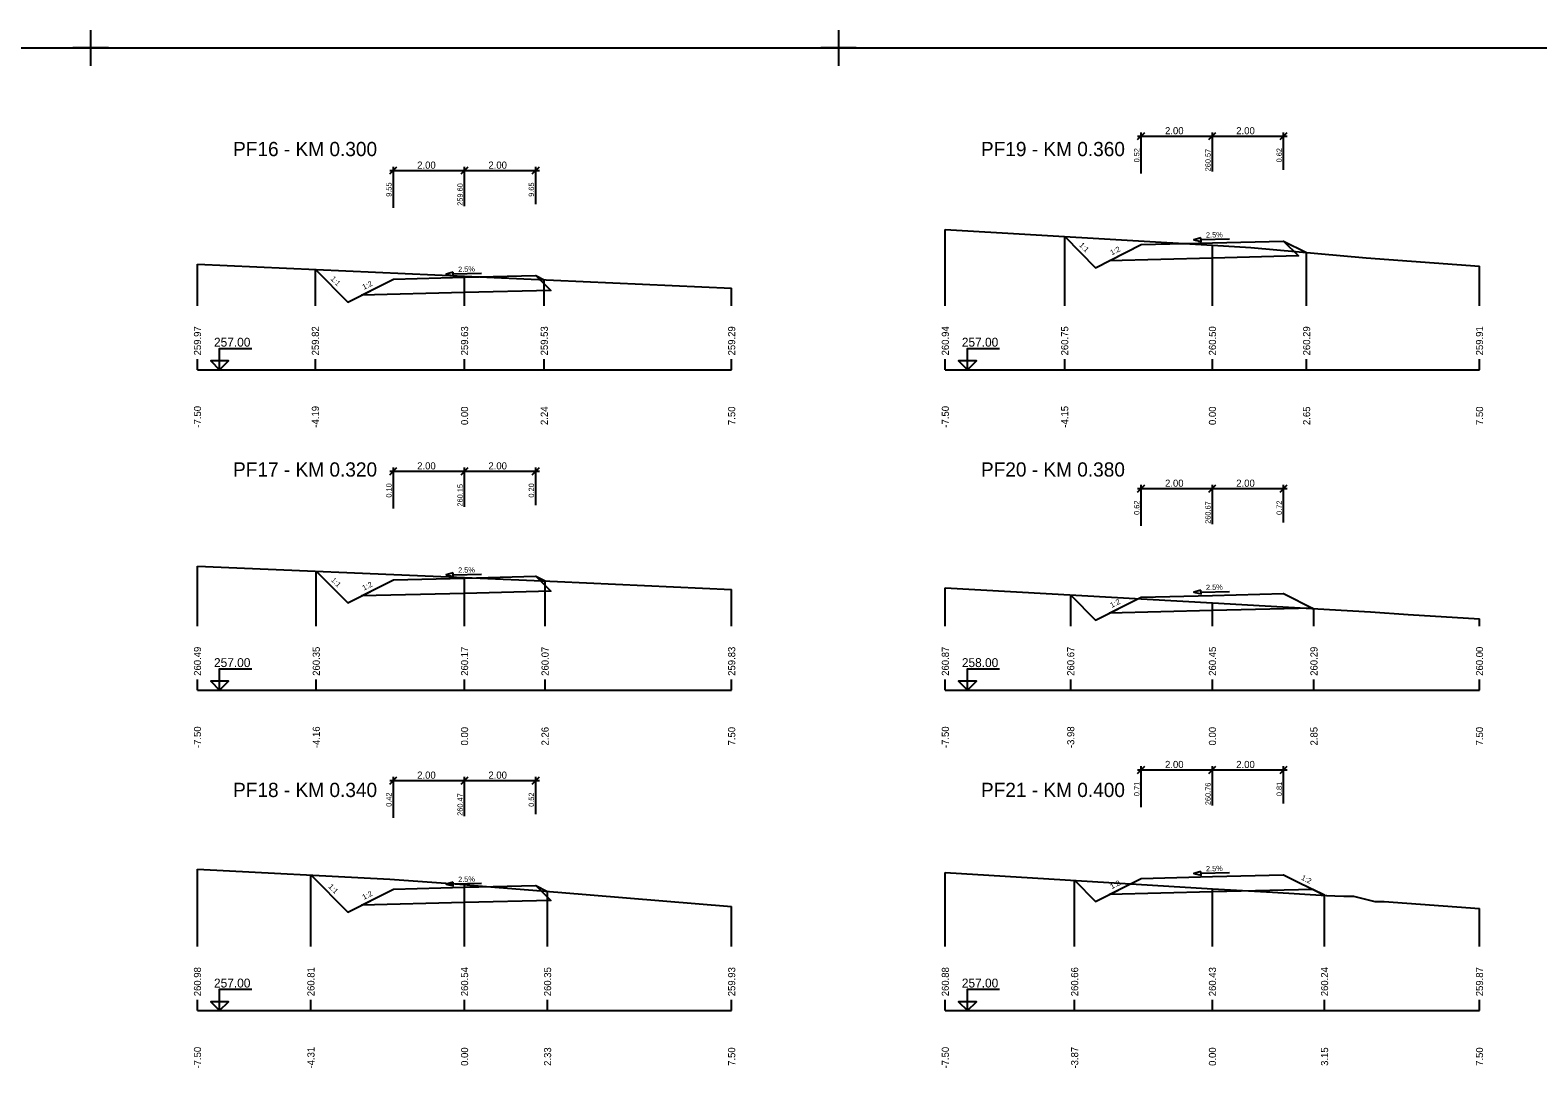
# Model space of a CAD drawing. Extents: x -5 to 1895, y -2 to 602.
# Drawn here: x 1033 to 1456.4, y 308.1 to 602.4 of the extents above; entities that cross this region are included whole.
import ezdxf

# ---------------------------------------------------------------- set-up
doc = ezdxf.new("R2010")
doc.units = 0
for name, color, linetype in [('KOTA', 7, 'Continuous'), ('KOTA_DELKY', 7, 'Continuous'), ('KOTA_DELKY_CONT', 7, 'Continuous'), ('NS_TELESO_VOZOVKY', 7, 'Continuous'), ('NS_V_PF', 7, 'Continuous'), ('REZY_PF_PUVODNI', 7, 'Continuous'), ('SESTAVY_REZU_PF', 7, 'Continuous'), ('SKLON', 7, 'Continuous'), ('SVK', 7, 'Continuous')]:
    doc.layers.add(name, color=color, linetype=linetype)

msp = doc.modelspace()

# ---------------------------------------------------------------- linework, layer by layer
for p, q in [((1050, 602.39), (1050, 592.39)), ((1050, 602.39), (1050, 592.39)), ((1050, 602.39), (1050, 592.39)), ((1050, 602.39), (1050, 592.39)), ((1050, 602.39), (1050, 592.39)), ((1050, 602.39), (1050, 592.39)), ((1050, 602.39), (1050, 592.39)), ((1050, 602.39), (1050, 592.39)), ((1050, 602.39), (1050, 592.39)), ((1050, 602.39), (1050, 592.39)), ((1050, 602.39), (1050, 592.39)), ((1050, 602.39), (1050, 592.39)), ((1050, 602.39), (1050, 592.39)), ((1050, 602.39), (1050, 592.39)), ((1050, 602.39), (1050, 592.39)), ((1050, 602.39), (1050, 592.39)), ((1050, 602.39), (1050, 592.39)), ((1050, 602.39), (1050, 592.39)), ((1260, 602.39), (1260, 592.39)), ((1260, 602.39), (1260, 592.39)), ((1260, 602.39), (1260, 592.39)), ((1260, 602.39), (1260, 592.39)), ((1260, 602.39), (1260, 592.39)), ((1260, 602.39), (1260, 592.39)), ((1260, 602.39), (1260, 592.39)), ((1260, 602.39), (1260, 592.39)), ((1260, 602.39), (1260, 592.39)), ((1260, 602.39), (1260, 592.39)), ((1260, 602.39), (1260, 592.39)), ((1260, 602.39), (1260, 592.39)), ((1260, 602.39), (1260, 592.39)), ((1260, 602.39), (1260, 592.39)), ((1260, 602.39), (1260, 592.39)), ((1260, 602.39), (1260, 592.39)), ((1260, 602.39), (1260, 592.39)), ((1260, 602.39), (1260, 592.39)), ((1055, 597.39), (1045, 597.39)), ((1055, 597.39), (1045, 597.39)), ((1055, 597.39), (1045, 597.39)), ((1055, 597.39), (1045, 597.39)), ((1055, 597.39), (1045, 597.39)), ((1055, 597.39), (1045, 597.39)), ((1055, 597.39), (1045, 597.39)), ((1055, 597.39), (1045, 597.39)), ((1055, 597.39), (1045, 597.39)), ((1055, 597.39), (1045, 597.39)), ((1055, 597.39), (1045, 597.39)), ((1055, 597.39), (1045, 597.39)), ((1055, 597.39), (1045, 597.39)), ((1055, 597.39), (1045, 597.39)), ((1055, 597.39), (1045, 597.39)), ((1055, 597.39), (1045, 597.39)), ((1055, 597.39), (1045, 597.39)), ((1055, 597.39), (1045, 597.39)), ((1265, 597.39), (1255, 597.39)), ((1265, 597.39), (1255, 597.39)), ((1265, 597.39), (1255, 597.39)), ((1265, 597.39), (1255, 597.39)), ((1265, 597.39), (1255, 597.39)), ((1265, 597.39), (1255, 597.39)), ((1265, 597.39), (1255, 597.39)), ((1265, 597.39), (1255, 597.39)), ((1265, 597.39), (1255, 597.39)), ((1265, 597.39), (1255, 597.39)), ((1265, 597.39), (1255, 597.39)), ((1265, 597.39), (1255, 597.39)), ((1265, 597.39), (1255, 597.39)), ((1265, 597.39), (1255, 597.39)), ((1265, 597.39), (1255, 597.39)), ((1265, 597.39), (1255, 597.39)), ((1265, 597.39), (1255, 597.39)), ((1265, 597.39), (1255, 597.39))]:
    msp.add_line(p, q)
msp.add_lwpolyline([(0, 597.39), (1890, 597.39), (1890, 3.39), (0, 3.39)], close=True)
at = {"layer": 'KOTA'}
for points in [[(1086.22, 509.5), (1083.72, 509.5), (1086.22, 507), (1086.22, 513), (1095.22, 513)], [(1296.22, 509.5), (1293.72, 509.5), (1296.22, 507), (1296.22, 513), (1305.22, 513)], [(1086.22, 507), (1088.72, 509.5), (1086.22, 509.5)], [(1296.22, 507), (1298.72, 509.5), (1296.22, 509.5)], [(1086.22, 419.5), (1083.72, 419.5), (1086.22, 417), (1086.22, 423), (1095.22, 423)], [(1086.22, 417), (1088.72, 419.5), (1086.22, 419.5)], [(1296.22, 419.5), (1293.72, 419.5), (1296.22, 417), (1296.22, 423), (1305.22, 423)], [(1296.22, 417), (1298.72, 419.5), (1296.22, 419.5)], [(1086.22, 329.5), (1083.72, 329.5), (1086.22, 327), (1086.22, 333), (1095.22, 333)], [(1296.22, 329.5), (1293.72, 329.5), (1296.22, 327), (1296.22, 333), (1305.22, 333)], [(1086.22, 327), (1088.72, 329.5), (1086.22, 329.5)], [(1296.22, 327), (1298.72, 329.5), (1296.22, 329.5)]]:
    msp.add_lwpolyline(points, dxfattribs=at)
at = {"layer": 'KOTA_DELKY'}
for points in [[(1344, 571.65), (1346, 573.65)], [(1344, 572.65), (1366, 572.65)], [(1345, 562.15), (1345, 573.65)], [(1364, 571.65), (1366, 573.65)], [(1364, 571.65), (1366, 573.65)], [(1364, 572.65), (1386, 572.65)], [(1365, 562.65), (1365, 573.65)], [(1365, 562.65), (1365, 573.65)], [(1384, 571.65), (1386, 573.65)], [(1385, 563.15), (1385, 573.65)], [(1134, 561.99), (1136, 563.99)], [(1135, 552.49), (1135, 563.99)], [(1154, 561.99), (1156, 563.99)], [(1154, 561.99), (1156, 563.99)], [(1155, 552.99), (1155, 563.99)], [(1155, 552.99), (1155, 563.99)], [(1174, 561.99), (1176, 563.99)], [(1175, 553.49), (1175, 563.99)], [(1134, 562.99), (1156, 562.99)], [(1154, 562.99), (1176, 562.99)], [(1134, 477.51), (1136, 479.51)], [(1134, 478.51), (1156, 478.51)], [(1135, 468.01), (1135, 479.51)], [(1154, 477.51), (1156, 479.51)], [(1154, 477.51), (1156, 479.51)], [(1154, 478.51), (1176, 478.51)], [(1155, 468.51), (1155, 479.51)], [(1155, 468.51), (1155, 479.51)], [(1174, 477.51), (1176, 479.51)], [(1175, 469.01), (1175, 479.51)], [(1344, 472.65), (1346, 474.65)], [(1345, 463.15), (1345, 474.65)], [(1364, 472.65), (1366, 474.65)], [(1364, 472.65), (1366, 474.65)], [(1365, 463.65), (1365, 474.65)], [(1365, 463.65), (1365, 474.65)], [(1384, 472.65), (1386, 474.65)], [(1385, 464.15), (1385, 474.65)], [(1344, 473.65), (1366, 473.65)], [(1364, 473.65), (1386, 473.65)], [(1344, 393.65), (1346, 395.65)], [(1344, 394.65), (1366, 394.65)], [(1345, 384.15), (1345, 395.65)], [(1364, 393.65), (1366, 395.65)], [(1364, 393.65), (1366, 395.65)], [(1364, 394.65), (1386, 394.65)], [(1365, 384.65), (1365, 395.65)], [(1365, 384.65), (1365, 395.65)], [(1384, 393.65), (1386, 395.65)], [(1385, 385.15), (1385, 395.65)], [(1134, 390.66), (1136, 392.66)], [(1134, 391.66), (1156, 391.66)], [(1135, 381.16), (1135, 392.66)], [(1154, 390.66), (1156, 392.66)], [(1154, 390.66), (1156, 392.66)], [(1154, 391.66), (1176, 391.66)], [(1155, 381.66), (1155, 392.66)], [(1155, 381.66), (1155, 392.66)], [(1174, 390.66), (1176, 392.66)], [(1175, 382.16), (1175, 392.66)]]:
    msp.add_lwpolyline(points, dxfattribs=at)
at = {"layer": 'NS_TELESO_VOZOVKY'}
for points in [[(1365, 542.65), (1385, 543.15), (1385, 543.15), (1389.2, 538.96), (1365, 538.35), (1336.05, 537.63), (1345, 542.15), (1345, 542.15), (1365, 542.65)], [(1155, 532.99), (1175, 533.49), (1175, 533.49), (1179.2, 529.3), (1155, 528.69), (1126.05, 527.97), (1135, 532.49), (1135, 532.49), (1155, 532.99)], [(1155, 448.51), (1175, 449.01), (1175, 449.01), (1179.2, 444.82), (1155, 444.21), (1126.05, 443.49), (1135, 448.01), (1135, 448.01), (1155, 448.51)], [(1365, 443.65), (1385, 444.15), (1385, 444.15), (1393.51, 439.9), (1393.19, 440.06), (1365, 439.35), (1336.05, 438.63), (1345, 443.15), (1345, 443.15), (1365, 443.65)], [(1365, 364.65), (1385, 365.15), (1385, 365.15), (1396.49, 359.4), (1393.19, 361.05), (1365, 360.35), (1336.05, 359.62), (1345, 364.15), (1345, 364.15), (1365, 364.65)], [(1155, 361.66), (1175, 362.16), (1175, 362.16), (1179.2, 357.96), (1155, 357.36), (1126.05, 356.63), (1135, 361.16), (1135, 361.16), (1155, 361.66)]]:
    msp.add_lwpolyline(points, dxfattribs=at)
at = {"layer": 'NS_V_PF'}
for points in [[(1323.51, 544.45), (1332.19, 535.68), (1345, 542.15), (1345, 542.15), (1365, 542.65), (1385, 543.15), (1385, 543.15), (1391.45, 539.93)], [(1113.11, 535.19), (1122.19, 526.02), (1135, 532.49), (1135, 532.49), (1155, 532.99), (1175, 533.49), (1175, 533.49), (1177.39, 532.3)], [(1113.36, 450.46), (1122.19, 441.54), (1135, 448.01), (1135, 448.01), (1155, 448.51), (1175, 449.01), (1175, 449.01), (1177.6, 447.71)], [(1325.21, 443.73), (1332.19, 436.67), (1345, 443.15), (1345, 443.15), (1365, 443.65), (1385, 444.15), (1385, 444.15), (1393.51, 439.9)], [(1111.86, 365.11), (1122.19, 354.68), (1135, 361.16), (1135, 361.16), (1155, 361.66), (1175, 362.16), (1175, 362.16), (1178.31, 360.5)], [(1326.31, 363.61), (1332.19, 357.67), (1345, 364.15), (1345, 364.15), (1365, 364.65), (1385, 365.15), (1385, 365.15), (1396.49, 359.4)]]:
    msp.add_lwpolyline(points, dxfattribs=at)
at = {"layer": 'REZY_PF_PUVODNI'}
for points in [[(1290, 546.44), (1365, 541.99), (1375.75, 541.35), (1408.2, 538.41), (1440, 536.09)], [(1080, 536.68), (1155, 533.3), (1230, 529.93)], [(1080, 451.88), (1155, 448.68), (1181.1, 447.56), (1230, 445.3)], [(1290, 445.71), (1365, 441.5), (1409.41, 439), (1419.95, 438.25), (1440, 437.04)], [(1080, 366.77), (1134, 363.96), (1155, 362.39), (1156.47, 362.28), (1181.15, 360.27), (1230, 356.28)], [(1290, 365.81), (1365, 361.26), (1381.84, 360.24), (1397.01, 359.37), (1397.09, 359.3), (1397.16, 359.37), (1399.36, 359.23), (1401.87, 359.2), (1404.63, 359.17), (1410.63, 357.66), (1413.23, 357.64), (1440, 355.68)]]:
    msp.add_lwpolyline(points, dxfattribs=at)
at = {"layer": 'SESTAVY_REZU_PF'}
for points in [[(1080, 507), (1230, 507)], [(1290, 507), (1440, 507)], [(1080, 417), (1230, 417)], [(1290, 417), (1440, 417)], [(1080, 327), (1230, 327)], [(1290, 327), (1440, 327)]]:
    msp.add_lwpolyline(points, dxfattribs=at)
at = {"layer": 'SKLON'}
for points in [[(1361.79, 544.07), (1359.8, 543.52), (1361.81, 543.07), (1361.79, 544.07)], [(1361.8, 543.57), (1369.8, 543.77)], [(1151.79, 534.41), (1149.8, 533.86), (1151.81, 533.41), (1151.79, 534.41)], [(1151.8, 533.91), (1159.8, 534.11)], [(1151.79, 449.93), (1149.8, 449.38), (1151.81, 448.93), (1151.79, 449.93)], [(1151.8, 449.43), (1159.8, 449.63)], [(1361.79, 445.07), (1359.8, 444.52), (1361.81, 444.07), (1361.79, 445.07)], [(1361.8, 444.57), (1369.8, 444.77)], [(1361.79, 366.07), (1359.8, 365.52), (1361.81, 365.07), (1361.79, 366.07)], [(1361.8, 365.57), (1369.8, 365.77)], [(1151.79, 363.08), (1149.8, 362.53), (1151.81, 362.08), (1151.79, 363.08)], [(1151.8, 362.58), (1159.8, 362.78)]]:
    msp.add_lwpolyline(points, dxfattribs=at)
at = {"layer": 'SVK'}
for points in [[(1290, 525), (1290, 546.44)], [(1323.51, 525), (1323.51, 544.45)], [(1365, 525), (1365, 541.99)], [(1391.45, 525), (1391.45, 539.93)], [(1080, 525), (1080, 536.68)], [(1113.11, 525), (1113.11, 535.19)], [(1440, 525), (1440, 536.09)], [(1155, 525), (1155, 533.3)], [(1177.39, 525), (1177.39, 532.3)], [(1230, 525), (1230, 529.93)], [(1080, 507), (1080, 510)], [(1113.11, 507), (1113.11, 510)], [(1155, 507), (1155, 510)], [(1177.39, 507), (1177.39, 510)], [(1230, 507), (1230, 510)], [(1290, 507), (1290, 510)], [(1323.51, 507), (1323.51, 510)], [(1365, 507), (1365, 510)], [(1391.45, 507), (1391.45, 510)], [(1440, 507), (1440, 510)], [(1080, 435), (1080, 451.88)], [(1113.36, 435), (1113.36, 450.46)], [(1155, 435), (1155, 448.68)], [(1177.6, 435), (1177.6, 447.71)], [(1230, 435), (1230, 445.3)], [(1290, 435), (1290, 445.71)], [(1325.21, 435), (1325.21, 443.73)], [(1365, 435), (1365, 441.5)], [(1393.51, 435), (1393.51, 439.9)], [(1440, 435), (1440, 437.04)], [(1080, 417), (1080, 420)], [(1113.36, 417), (1113.36, 420)], [(1155, 417), (1155, 420)], [(1177.6, 417), (1177.6, 420)], [(1230, 417), (1230, 420)], [(1290, 417), (1290, 420)], [(1325.21, 417), (1325.21, 420)], [(1365, 417), (1365, 420)], [(1393.51, 417), (1393.51, 420)], [(1440, 417), (1440, 420)], [(1080, 345), (1080, 366.77)], [(1111.86, 345), (1111.86, 365.11)], [(1290, 345), (1290, 365.81)], [(1155, 345), (1155, 362.39)], [(1178.31, 345), (1178.31, 360.5)], [(1326.31, 345), (1326.31, 363.61)], [(1365, 345), (1365, 361.26)], [(1230, 345), (1230, 356.28)], [(1396.49, 345), (1396.49, 359.4)], [(1440, 345), (1440, 355.68)], [(1080, 327), (1080, 330)], [(1111.86, 327), (1111.86, 330)], [(1155, 327), (1155, 330)], [(1178.31, 327), (1178.31, 330)], [(1230, 327), (1230, 330)], [(1290, 327), (1290, 330)], [(1326.31, 327), (1326.31, 330)], [(1365, 327), (1365, 330)], [(1396.49, 327), (1396.49, 330)], [(1440, 327), (1440, 330)]]:
    msp.add_lwpolyline(points, dxfattribs=at)

# ---------------------------------------------------------------- texts
at = {"layer": 'KOTA'}
for s, p in [('257.00', (1084.64, 513.5)), ('257.00', (1294.64, 513.5)), ('257.00', (1084.64, 423.5)), ('258.00', (1294.64, 423.5)), ('257.00', (1084.64, 333.5)), ('257.00', (1294.64, 333.5))]:
    msp.add_text(s, height=2.5, dxfattribs=at).set_placement(p)
at = {"layer": 'KOTA_DELKY'}
for p in [(1351.69, 573.15), (1371.69, 573.15), (1141.69, 563.49), (1161.69, 563.49), (1141.69, 479.01), (1161.69, 479.01), (1351.69, 474.15), (1371.69, 474.15), (1141.69, 392.16), (1161.69, 392.16), (1351.69, 395.15), (1371.69, 395.15)]:
    msp.add_text('2.00', height=2, dxfattribs=at).set_placement(p)
at = {"layer": 'KOTA_DELKY_CONT'}
for s, p in [('0.52', (1344.5, 565.24)), ('260.57', (1364.5, 562.73)), ('0.62', (1384.5, 565.24)), ('9.55', (1134.5, 555.58)), ('259.60', (1154.5, 553.07)), ('9.65', (1174.5, 555.58)), ('0.10', (1134.5, 471.1)), ('260.15', (1154.5, 468.59)), ('0.20', (1174.5, 471.1)), ('0.62', (1344.5, 466.24)), ('0.72', (1384.5, 466.24)), ('260.67', (1364.5, 463.73)), ('0.71', (1344.5, 387.24)), ('260.76', (1364.5, 384.72)), ('0.81', (1384.5, 387.24)), ('0.42', (1134.5, 384.25)), ('260.47', (1154.5, 381.73)), ('0.52', (1174.5, 384.25))]:
    msp.add_text(s, height=1.5, rotation=90, dxfattribs=at).set_placement(p)
at = {"layer": 'SESTAVY_REZU_PF'}
for s, p in [('PF16 - KM 0.300', (1090, 567)), ('PF19 - KM 0.360', (1300, 567)), ('PF17 - KM 0.320', (1090, 477)), ('PF20 - KM 0.380', (1300, 477)), ('PF18 - KM 0.340', (1090, 387)), ('PF21 - KM 0.400', (1300, 387))]:
    msp.add_text(s, height=4, dxfattribs=at).set_placement(p)
at = {"layer": 'SKLON'}
for s, rotation, p in [('1:1', 314.7121, (1327.45, 541.89)), ('2.5%', 1.4321, (1363.2, 544.11)), ('1:2', 26.8233, (1336.74, 539.1)), ('2.5%', 1.4321, (1153.2, 534.45)), ('1:1', 314.7121, (1117.25, 532.43)), ('1:2', 26.8233, (1126.74, 529.44)), ('2.5%', 1.4321, (1153.2, 449.97)), ('1:1', 314.7121, (1117.38, 447.82)), ('1:2', 26.8233, (1126.74, 444.96)), ('2.5%', 1.4321, (1363.2, 445.11)), ('1:2', 26.8233, (1336.74, 440.09)), ('2.5%', 1.4321, (1153.2, 363.11)), ('2.5%', 1.4321, (1363.2, 366.1)), ('1:2', 333.4349, (1389.78, 363.87)), ('1:1', 314.7121, (1116.63, 361.72)), ('1:2', 26.8233, (1126.74, 358.1)), ('1:2', 26.8233, (1336.74, 361.09))]:
    msp.add_text(s, height=1.5, rotation=rotation, dxfattribs=at).set_placement(p)
at = {"layer": 'SVK'}
for s, p in [(' 259.97', (1081, 510.3)), (' 259.82', (1114.11, 510.3)), (' 259.63', (1156, 510.3)), (' 259.53', (1178.39, 510.3)), (' 259.29', (1231, 510.3)), (' 260.94', (1291, 510.3)), (' 260.75', (1324.51, 510.3)), (' 260.50', (1366, 510.3)), (' 260.29', (1392.45, 510.3)), (' 259.91', (1441, 510.3)), (' -7.50', (1081, 490)), (' -4.19', (1114.11, 490)), ('  0.00', (1156, 490)), ('  2.24', (1178.39, 490)), ('  7.50', (1231, 490)), (' -7.50', (1291, 490)), (' -4.15', (1324.51, 490)), ('  0.00', (1366, 490)), ('  2.65', (1392.45, 490)), ('  7.50', (1441, 490)), (' 260.49', (1081, 420.3)), (' 260.35', (1114.36, 420.3)), (' 260.17', (1156, 420.3)), (' 260.07', (1178.6, 420.3)), (' 259.83', (1231, 420.3)), (' 260.87', (1291, 420.3)), (' 260.67', (1326.21, 420.3)), (' 260.45', (1366, 420.3)), (' 260.29', (1394.51, 420.3)), (' 260.00', (1441, 420.3)), (' -7.50', (1081, 400)), (' -4.16', (1114.36, 400)), ('  0.00', (1156, 400)), ('  2.26', (1178.6, 400)), ('  7.50', (1231, 400)), (' -7.50', (1291, 400)), (' -3.98', (1326.21, 400)), ('  0.00', (1366, 400)), ('  2.85', (1394.51, 400)), ('  7.50', (1441, 400)), (' 260.98', (1081, 330.3)), (' 260.81', (1112.86, 330.3)), (' 260.54', (1156, 330.3)), (' 260.35', (1179.31, 330.3)), (' 259.93', (1231, 330.3)), (' 260.88', (1291, 330.3)), (' 260.66', (1327.31, 330.3)), (' 260.43', (1366, 330.3)), (' 260.24', (1397.49, 330.3)), (' 259.87', (1441, 330.3)), (' -7.50', (1081, 310)), (' -4.31', (1112.86, 310)), ('  0.00', (1156, 310)), ('  2.33', (1179.31, 310)), ('  7.50', (1231, 310)), (' -7.50', (1291, 310)), (' -3.87', (1327.31, 310)), ('  0.00', (1366, 310)), ('  3.15', (1397.49, 310)), ('  7.50', (1441, 310))]:
    msp.add_text(s, height=2, rotation=90, dxfattribs=at).set_placement(p)

doc.saveas('drawing.dxf')
